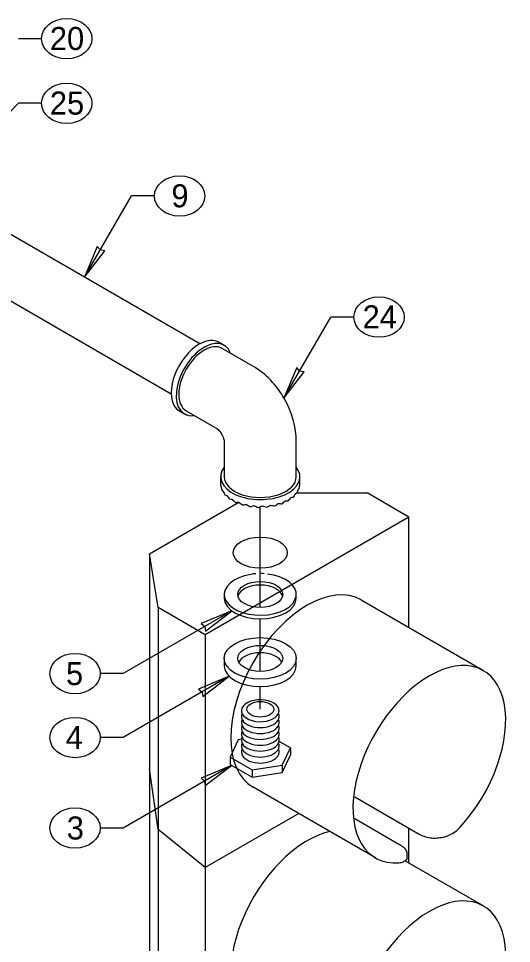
# Model space of a CAD drawing. Extents: x 99862 to 104211, y 98939 to 105076.
# Drawn here: x 102115 to 102457, y 103854 to 104496 of the extents above; entities that cross this region are included whole.
import ezdxf

# ---------------------------------------------------------------- set-up
doc = ezdxf.new("R2010")
doc.units = 0
for name, color, linetype in [('Level 11', 7, 'Continuous'), ('Level 15', 7, 'Continuous'), ('Level 19', 7, 'Continuous'), ('Level 2', 7, 'Continuous'), ('Level 20', 7, 'Continuous'), ('Level 26', 7, 'Continuous'), ('Level 3', 7, 'Continuous'), ('Level 4', 7, 'Continuous'), ('Level 5', 7, 'Continuous'), ('Level 7', 7, 'Continuous')]:
    doc.layers.add(name, color=color, linetype=linetype)

msp = doc.modelspace()

# ---------------------------------------------------------------- linework, layer by layer
at = {"layer": 'Level 11'}
for p, q in [((102257.42, 104096.66), (102257.42, 104094.11)), ((102307.42, 104094.11), (102307.42, 104096.66)), ((102257.42, 104052.27), (102257.42, 104047.16)), ((102307.42, 104047.16), (102307.42, 104052.27))]:
    msp.add_line(p, q, dxfattribs=at)
for centre in [(102282.42, 104096.66), (102282.42, 104052.27)]:
    msp.add_ellipse(centre, major_axis=(-15.62, 0), ratio=0.57735, dxfattribs=at)
for centre, major_axis, start_param, end_param in [((102282.42, 104096.66), (-25, 0), 4.832309, 4.979655), ((102282.42, 104096.66), (-25, 0), 4.606495, 4.687473), ((102282.42, 104094.11), (15.62, 0), 0.141897, 2.999696), ((102282.42, 104094.11), (25, 0), 3.141593, 6.283185), ((102282.42, 104047.16), (15.62, 0), 0.286757, 2.854836), ((102282.42, 104047.16), (25, 0), 3.141593, 6.283185)]:
    msp.add_ellipse(centre, major_axis=major_axis, ratio=0.57735, start_param=start_param, end_param=end_param, dxfattribs=at)
at = {"layer": 'Level 15'}
for p, q in [((102130.56, 104482.17), (102114.56, 104482.17)), ((102059.05, 104381.05), (102114.56, 104437.35)), ((102130.56, 104437.35), (102114.56, 104437.35)), ((102160.42, 104316.75), (102192.92, 104373.04)), ((102208.92, 104373.04), (102192.92, 104373.04)), ((102298.9, 104232.74), (102331.4, 104289.03)), ((102347.4, 104289.03), (102331.4, 104289.03)), ((102282.43, 104087.64), (102282.43, 104157.51)), ((102262.7, 104085.24), (102187.35, 104041.74)), ((102282.43, 104043.25), (102282.43, 104079.68)), ((102187.35, 104041.74), (102171.35, 104041.74)), ((102260.89, 104039.83), (102187.35, 103997.37)), ((102282.43, 104016.96), (102282.43, 104032.73)), ((102187.35, 103997.37), (102171.35, 103997.37)), ((102262.54, 103978.02), (102187.35, 103934.61)), ((102187.35, 103934.61), (102171.35, 103934.61))]:
    msp.add_line(p, q, dxfattribs=at)
for points in [[(102160.42, 104316.75), (102174.42, 104335.03), (102171.31, 104335.61), (102169.25, 104338.02)], [(102298.9, 104232.74), (102312.9, 104251.01), (102309.78, 104251.59), (102307.73, 104254)], [(102262.7, 104085.24), (102241.44, 104076.41), (102243.84, 104074.35), (102244.42, 104071.24)], [(102260.89, 104039.83), (102239.62, 104031), (102242.03, 104028.94), (102242.61, 104025.83)], [(102262.54, 103978.02), (102241.28, 103969.19), (102243.68, 103967.13), (102244.26, 103964.02)]]:
    msp.add_lwpolyline(points, close=True, dxfattribs=at)
at = {"layer": 'Level 19'}
for p, q in [((102211.49, 103933.6), (102205.62, 103975.6)), ((102244.26, 103907.12), (102211.49, 103933.6))]:
    msp.add_line(p, q, dxfattribs=at)
at = {"layer": 'Level 2'}
for p, q in [((102297.73, 103978.11), (102303.33, 103990.19)), ((102261.51, 103983.72), (102276.81, 103974.88)), ((102276.81, 103974.88), (102297.73, 103978.11)), ((102297.73, 103978.11), (102297.73, 103973.01)), ((102276.81, 103974.88), (102276.81, 103969.77))]:
    msp.add_line(p, q, dxfattribs=at)
msp.add_ellipse((102282.42, 104016.96), major_axis=(9.38, 0), ratio=0.57735, dxfattribs=at)
for centre, start_param, end_param in [((102282.42, 104011.85), 6.010442, 9.697521), ((102282.42, 104007.77), 6.010442, 9.697521), ((102282.42, 104003.61), 6.004973, 9.70299), ((102282.42, 103995.52), 6.010442, 9.697521), ((102282.42, 103999.61), 6.015903, 9.69206), ((102282.42, 103991.44), 6.010442, 9.697521)]:
    msp.add_ellipse(centre, major_axis=(-13.12, 0), ratio=0.57735, start_param=start_param, end_param=end_param, dxfattribs=at)
at = {"layer": 'Level 20'}
for p, q in [((102240.55, 104270.49), (102080.29, 104363.02)), ((102060.29, 104328.38), (102220.55, 104235.85)), ((102277.24, 104255.08), (102256.03, 104267.33)), ((102231.03, 104224.03), (102252.24, 104211.78)), ((102257.42, 104202.81), (102257.42, 104178.32)), ((102307.42, 104178.32), (102307.42, 104202.81)), ((102254.92, 104178.32), (102254.92, 104173.38)), ((102309.92, 104173.38), (102309.92, 104178.32))]:
    msp.add_line(p, q, dxfattribs=at)
for centre in [(102148.06, 104482.17), (102148.06, 104437.35), (102226.42, 104373.04), (102364.9, 104289.03), (102153.85, 104041.74), (102153.85, 103997.37), (102153.85, 103934.61)]:
    msp.add_ellipse(centre, major_axis=(-17.5, 0), ratio=0.8, dxfattribs=at)
for centre, major_axis, ratio, start_param, end_param in [((102239.99, 104247.72), (13.75, 23.82), 0.57735, 0, 3.141593), ((102282.42, 104173.92), (-27.03, -5.37), 0.947565, 6.097095, 6.149455), ((102282.42, 104173.92), (-27.5, -1.68), 0.206802, 0.039705, 0.144424), ((102282.42, 104173.92), (25.29, -11.7), 0.922162, 3.702024, 3.806744), ((102282.42, 104173.92), (-24.4, -14.28), 0.888613, 2.295514, 2.400234), ((102282.42, 104173.92), (27.49, -2.79), 0.213589, 6.04308, 6.1478), ((102282.42, 104173.92), (-27.03, -5.37), 0.947565, 2.798423, 2.903143), ((102282.42, 104173.92), (-27.49, -3.89), 0.223561, 0.230203, 0.334923), ((102282.42, 104173.92), (24.12, -15.48), 0.853385, 4.009326, 4.114045), ((102282.42, 104173.92), (-27.46, -6), 0.252109, 0.416228, 0.520948), ((102282.42, 104173.92), (24.3, -16.43), 0.783391, 4.204501, 4.309221), ((102282.42, 104173.92), (-24.54, -16.55), 0.749264, 1.888318, 1.993037), ((102282.42, 104173.92), (27.43, -7.01), 0.270119, 5.671382, 5.776101), ((102282.42, 104173.92), (-24.14, -16.11), 0.818147, 2.06586, 2.17058), ((102282.42, 104173.92), (27.48, -4.96), 0.236491, 5.854579, 5.959298), ((102282.42, 104173.92), (-27.4, -7.98), 0.290225, 0.596374, 0.701094), ((102282.42, 104173.92), (24.82, -16.54), 0.715795, 4.372134, 4.476854), ((102282.42, 104173.92), (-27.3, -9.8), 0.335596, 0.770216, 0.874936), ((102282.42, 104173.92), (25.39, -16.22), 0.650745, 4.530376, 4.635096), ((102282.42, 104173.92), (-27.14, -11.45), 0.386234, 0.938087, 1.042807), ((102282.42, 104173.92), (25.93, -15.58), 0.588004, 4.685558, 4.790278), ((102282.42, 104173.92), (-26.91, -12.9), 0.440657, 1.100807, 1.205527), ((102282.42, 104173.92), (26.39, -14.68), 0.527399, 4.840753, 4.945473), ((102282.42, 104173.92), (-26.58, -14.14), 0.497899, 1.259485, 1.364205), ((102282.42, 104173.92), (26.76, -13.55), 0.468967, 4.997892, 5.102266), ((102282.42, 104173.92), (-26.18, -15.07), 0.558157, 1.416585, 1.52165), ((102282.42, 104173.92), (27.04, -12.13), 0.414287, 5.15799, 5.263055), ((102282.42, 104173.92), (-25.67, -15.94), 0.6191, 1.570694, 1.675068), ((102282.42, 104173.92), (27.23, -10.65), 0.360362, 5.323611, 5.42833), ((102282.42, 104173.92), (-25.11, -16.43), 0.682966, 1.726553, 1.831273), ((102282.42, 104173.92), (27.36, -8.91), 0.312139, 5.494389, 5.599109)]:
    msp.add_ellipse(centre, major_axis=major_axis, ratio=ratio, start_param=start_param, end_param=end_param, dxfattribs=at)
for points in [[(102307.42, 104202.81), (102307.41, 104212.51), (102301.37, 104233.48), (102286.42, 104249.78), (102277.24, 104255.08)], [(102252.24, 104211.78), (102252.1, 104211.87), (102253.57, 104211), (102256.52, 104206.4), (102257.45, 104203.13), (102257.41, 104202.71), (102257.42, 104202.81)]]:
    msp.add_open_spline(points, degree=3, dxfattribs=at)
at = {"layer": 'Level 26'}
for p, q in [((102307.96, 104167.1), (102356.62, 104167.1)), ((102385.68, 104150.32), (102356.62, 104167.1)), ((102205.62, 104124.89), (102267.46, 104160.59)), ((102385.68, 104150.32), (102244.26, 104068.67)), ((102385.68, 104073.63), (102385.68, 104150.32)), ((102211.49, 104087.59), (102205.62, 104124.89)), ((102205.62, 104124.89), (102205.62, 103634.99)), ((102352.47, 104092.8), (102437.32, 104043.81)), ((102244.26, 104068.67), (102211.49, 104087.59)), ((102211.49, 104087.59), (102211.49, 103597.69)), ((102244.26, 104068.67), (102244.26, 103578.78)), ((102362.32, 103913.91), (102277.47, 103962.9)), ((102348.05, 103956.22), (102392.75, 103930.42)), ((102309.17, 103944.59), (102244.26, 103907.12)), ((102378.61, 103923.28), (102348.15, 103940.86)), ((102385.68, 103910.33), (102385.68, 103934.5)), ((102384.46, 103914.93), (102384.46, 103915.97)), ((102382.95, 103911.9), (102437.32, 103880.51))]:
    msp.add_line(p, q, dxfattribs=at)
msp.add_ellipse((102282.42, 104125.59), major_axis=(18.75, 0), ratio=0.57735, dxfattribs=at)
for centre, start_param, end_param in [((102314.97, 104027.85), 3.141593, 6.283185), ((102399.82, 103978.86), 1.196915, 6.657067), ((102314.97, 103864.55), 3.624566, 6.283185), ((102399.82, 103815.56), 1.196915, 6.657067)]:
    msp.add_ellipse(centre, major_axis=(-37.5, -64.95), ratio=0.57735, start_param=start_param, end_param=end_param, dxfattribs=at)
for points, degree in [([(102392.75, 103930.42), (102394.66, 103929.31), (102396.93, 103928.51), (102401.89, 103927.62), (102404.57, 103927.55), (102409.84, 103928.28), (102412.46, 103929.08), (102417.17, 103931.48), (102419.28, 103933.09), (102421.03, 103934.98)], 3), ([(102384.46, 103915.96), (102384.46, 103918.29), (102382.36, 103921.12), (102378.61, 103923.28)], 2), ([(102378.61, 103910.49), (102380.36, 103910.61), (102381.8, 103911.06), (102383.84, 103912.56), (102384.42, 103913.59), (102384.46, 103914.81), (102384.46, 103914.85), (102384.46, 103914.88)], 3)]:
    msp.add_open_spline(points, degree=degree, dxfattribs=at)
at = {"layer": 'Level 3'}
for p, q in [((102267.11, 103995.79), (102261.51, 103983.72)), ((102269.34, 103996.13), (102267.11, 103995.79)), ((102303.33, 103990.19), (102295.47, 103994.73)), ((102303.33, 103990.19), (102303.33, 103985.08)), ((102261.51, 103983.72), (102261.51, 103978.61)), ((102297.73, 103973.01), (102303.33, 103985.08)), ((102261.51, 103978.61), (102276.81, 103969.77)), ((102276.81, 103969.77), (102297.73, 103973.01))]:
    msp.add_line(p, q, dxfattribs=at)
for centre, start_param, end_param in [((102282.42, 104015.94), 5.832326, 12.115165), ((102282.42, 103987.27), 6.00421, 9.703753)]:
    msp.add_ellipse(centre, major_axis=(-13.12, 0), ratio=0.57735, start_param=start_param, end_param=end_param, dxfattribs=at)
at = {"layer": 'Level 4'}
msp.add_ellipse((102282.42, 104052.27), major_axis=(-25, 0), ratio=0.57735, dxfattribs=at)
at = {"layer": 'Level 5'}
msp.add_ellipse((102282.42, 104096.66), major_axis=(-25, 0), ratio=0.57735, start_param=4.979655, end_param=10.797393, dxfattribs=at)
at = {"layer": 'Level 7'}
for p, q in [((102257.28, 104269.49), (102253.74, 104271.53)), ((102226.24, 104223.9), (102229.78, 104221.86))]:
    msp.add_line(p, q, dxfattribs=at)
for centre, major_axis, ratio, start_param, end_param in [((102243.53, 104245.68), (13.75, 23.82), 0.57735, 5.853486, 9.854478), ((102243.53, 104245.68), (-12.5, -21.65), 0.57735, 3.141593, 6.283185), ((102282.42, 104178.32), (-27.5, 0), 0.57735, 5.853486, 9.854478), ((102282.42, 104178.32), (-25, 0), 0.57735, 0, 3.141593), ((102282.42, 104173.92), (27.5, -0.56), 0.203365, 6.234982, 6.287342)]:
    msp.add_ellipse(centre, major_axis=major_axis, ratio=ratio, start_param=start_param, end_param=end_param, dxfattribs=at)

# ---------------------------------------------------------------- texts
at = {"layer": 'Level 20'}
for s, p in [('20', (102136.36, 104474.3)), ('25', (102136.36, 104429.48)), ('9', (102220.76, 104365.18)), ('24', (102353.5, 104281.16)), ('5', (102147.54, 104033.74)), ('4', (102147.34, 103989.38)), ('3', (102148.07, 103926.61))]:
    msp.add_text(s, height=16, dxfattribs=at).set_placement(p)

doc.saveas('drawing.dxf')
